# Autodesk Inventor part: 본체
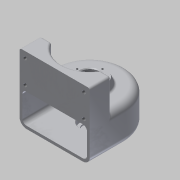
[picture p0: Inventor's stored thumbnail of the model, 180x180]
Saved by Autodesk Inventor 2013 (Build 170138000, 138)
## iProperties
Created: 2015-02
Part Number: 본체
Material: 알루미늄 6061
Document SubType Name: Modeling
Designer: Administrator
Density: 2.71 g/cm^3
Mass: 575.238 g
Surface Area: 710.538 cm^2
Volume: 212.265 cm^3
Author: Administrator
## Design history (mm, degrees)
sketch "스케치1"
  geometry: L1 (50, 0)-(50, -50); L2 (50, -50)-(-50, -50); L3 (-50, -50)-(-50, 0); A1 r 50 centre (0, 0) between (50, 0) and (-50, 0); 1 further point
  constraints: 6 end point, 2 point on circle, 2 tangent, 1 centre point, 1 coincident, 1 parallel, 1 perpendicular, 1 vertical
  dimensions: "d0" = 100 diameter of A1; "d1" = 50 distance of L1.start L1.end
extrude "돌출1" new body sketch "스케치1" stored distance "d2" = 50; taper "d3" = 0 deg
sketch "스케치2"
  geometry: L1 (0, 25)-(0, 35); L2 (50, 25)-(0, 25) reference; L3 (0, 35)-(21.36, 35); L4 (21.36, 35)-(25, 25); L5 (25, 25)-(0, 25); 1 further point
  constraints: 8 end point, 1 collinear, 1 midpoint, 1 parallel, 1 vertical, 1 vertical alignment
  dimensions: "d4" = 10 distance of L1.start L1.end; "d5" = 110 deg angle of L2 L4
revolve "회전1" sketch "스케치2" stored, may be unused: angle "d6" = 90 deg
sketch "스케치3"
  geometry: C1 r 20 at (0, 0); A1 r 50 centre (0, 0) between (50, 0) and (-50, 0) reference
  constraints: 1 centre point, 1 coincident
  dimensions: "d7" = 40 diameter of C1
extrude "돌출2" join sketch "스케치3" distance "d8" = 9; taper "d9" = 0 deg
sketch "스케치4"
  geometry: L1 (-50, 0)-(-50, -50) reference; L2 (-50, -50)-(50, -50) reference; L3 (50, -50)-(50, 0) reference; L4 (50, -50)-(50, -20); L5 (50, -20)-(34.641, -20); L6 (-50, -50)-(-50, -20); L7 (-50, -20)-(-34.641, -20); L8 (-50, -50)-(50, -50); A1 r 50 centre (0, 0) between (50, 0) and (-50, 0) reference; A2 r 40 centre (0, 0) between (-34.641, -20) and (34.641, -20)
  constraints: 10 end point, 2 perpendicular, 2 point on circle, 2 point on line, 1 centre point, 1 coincident, 1 parallel
  dimensions: "d10" = 80 diameter of A2; "d11" = 30 distance of L2.end L4.end; "d12" = 30 distance of L1.end L6.end
extrude "돌출3" join sketch "스케치4" distance "d13" = 45; taper "d14" = 0 deg
sketch "스케치5"
  geometry: L1 (0, 21)-(0, -21); L2 (0, 21)-(46, 21); L3 (46, 21)-(46, -21); L4 (46, -21)-(0, -21); L5 (50, -25)-(50, 25) reference; 2 further points
  constraints: 8 end point, 2 perpendicular, 1 coincident, 1 midpoint, 1 parallel, 1 vertical
  dimensions: "d15" = 42 distance of L1.start L1.end; "d16" = 4 distance between parallel lines of L5 L3
revolve "회전2" sketch "스케치5" stored, may be unused: angle "d17" = 90 deg
sketch "스케치6"
  geometry: L1 (100, 0)-(0, 0) reference; L2 (4, 46)-(96, 46); L3 (96, 46)-(96, 4); L4 (96, 4)-(4, 4); L5 (4, 4)-(4, 46); 3 further points
  constraints: 8 end point, 2 midpoint, 2 parallel, 1 horizontal, 1 perpendicular, 1 vertical alignment
  dimensions: "d18" = 4 distance between parallel lines of L4 L1; "d19" = 42 distance of L2.end L3.end; "d20" = 92 distance between parallel lines of L5 L3
extrude "돌출4" cut sketch "스케치6" distance "d21" = 50; taper "d22" = 0 deg
sketch "스케치7"
  geometry: L1 (-21.36, 35)-(21.36, 35) reference; L2 (-20, -34)-(20, -34) reference; L3 (46, -21)-(0, -21) reference; L4 (0, 35)-(0, -34); L5 (0, 35)-(14, 35); L6 (14, 35)-(14, 25); L7 (14, 25)-(10, 25); L8 (10, 25)-(10, -21); L9 (10, -21)-(14, -21); L10 (14, -21)-(14, -29); L11 (14, -29)-(10, -29); L12 (10, -29)-(10, -31); L13 (10, -31)-(0, -31); 1 further point
  constraints: 20 end point, 7 perpendicular, 4 point on line, 2 midpoint
  dimensions: "d23" = 28 diameter of L6 L4; "d25" = 20 diameter of L8 L4; "d26" = 10 distance between parallel lines of L1 L7; "d27" = 28 diameter of L10 L4; "d29" = 8 distance between parallel lines of L11 L3; "d30" = 2 distance of L11.end L12.end; "d31" = 20 diameter of L12 L4
revolve "회전3" sketch "스케치7" stored, may be unused: angle "d32" = 90 deg
sketch "스케치8"
  geometry: C1 r 14 at (0, 0) reference; 1 further point
  constraints: 1 vertical alignment
  dimensions: "d33" = 18 distance of C1.centre point (0, 18)
hole "구멍1" sketch "스케치8" at (0, 18) diameter "d34" = 2.459; stored, may be unused: countersink angle "d38" = 90 deg, drill point angle "d40" = 118 deg; dims "d35" = 6, "d36" = 4, "d37" = 2, "d39" = 9
sketch "스케치9"
  geometry: L1 (0, 95)-(100, 95) reference; L2 (0, 0)-(0, 95) reference; 5 further points
  constraints: 2 horizontal alignment, 2 vertical alignment
  dimensions: "d44" = 33 distance of point (8.25, 53) point (8.25, 86); "d46" = 83.5 distance of point (91.75, 86) point (8.25, 86); "d47" = 9 distance from line of L1 point (8.25, 86); "d48" = 8.25 distance from line of L2 point (8.25, 86)
hole "구멍2" sketch "스케치9" at (8.25, 86), (8.25, 53), (91.75, 53), (91.75, 86) diameter "d49" = 5.134; stored, may be unused: countersink angle "d53" = 90 deg, drill point angle "d55" = 118 deg; dims "d50" = 10, "d51" = 4, "d52" = 2, "d54" = 13
node "작업 평면1"
sketch "스케치10"
  geometry: L1 (-50, -25)-(50, -25) reference; 2 further points
  constraints: 1 coincident, 1 other
  dimensions: "d56" = 25 distance from line of point (0, 0) L1
feature "엠보싱1" sketch "스케치10" dims "d57" = 0.5, "d58" = 0
chamfer "모따기1" distance "d59" = 1; stored, may be unused: second distance "d60" = 2, angle "d61" = 45 deg
fillet "모깎기1" dims "d62" = 0.3
fillet "모깎기2" dims "d63" = 6
fillet "모깎기5" dims "d66" = 10
fillet "모깎기6" dims "d67" = 3
fillet "모깎기7" dims "d68" = 3
fillet "모깎기8" dims "d69" = 3
fillet "모깎기9" dims "d70" = 3
node "솔리드1"
pattern_circular "원형 패턴1" dims angle "d42" = 360 deg
